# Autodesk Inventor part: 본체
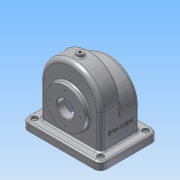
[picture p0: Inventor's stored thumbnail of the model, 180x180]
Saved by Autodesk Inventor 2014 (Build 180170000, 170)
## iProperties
Created: 2017-11
Part Number: 본체
Material: 알루미늄 6061
Document SubType Name: Modeling
Designer: sda
Density: 2.71 g/cm^3
Appearance: 알루미늄 - 평지
Mass: 1079.27 g
Surface Area: 1180.72 cm^2
Volume: 398.255 cm^3
Author: sda
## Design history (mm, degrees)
sketch "스케치1"
  geometry: L1 (-58, 0)-(58, 0); L2 (58, 0)-(58, -80); L3 (58, -80)-(-58, -80); L4 (-58, -80)-(-58, 0); C1 r 58 at (0, 0); 2 further points
  constraints: 8 end point, 2 coincident, 2 parallel, 1 centre point, 1 horizontal, 1 midpoint, 1 perpendicular
  dimensions: "d0" = 80 distance of L1.end L2.end; "d1" = 116 distance of L2.end L3.end; "d2" = 116 diameter of C1
extrude "돌출1" new body sketch "스케치1" distance "d3" = 38; taper "d4" = 0 deg
sketch "스케치2"
  geometry: L1 (-58, -80)-(58, -80) reference; L2 (58, -80)-(58, 0) reference; L3 (-58, -23)-(58, -23); L4 (58, -23)-(58, -80); L5 (58, -80)-(-58, -80); L6 (-58, -80)-(-58, -23); A1 r 58 centre (0, -23) between (58, -23) and (-10.724, -80); A2 r 58 centre (0, -23) between (10.724, -80) and (58, -23); A3 r 58 centre (0, -23) between (-10.724, -80) and (10.724, -80); 1 further point
  constraints: 8 end point, 6 point on circle, 3 centre point, 3 midpoint, 3 point on line, 2 parallel, 1 horizontal, 1 perpendicular
  dimensions: "d5" = 116 distance of L3.start L3.end; "d6" = 57 distance between parallel lines of L1 L3; "d8" = 58 radius of A2
extrude "돌출2" join sketch "스케치2" distance "d9" = 38; taper "d10" = 0 deg
sketch "스케치3"
  geometry: L1 (-58, -80)-(58, -80) reference; C1 r 37.5 at (0, -15); A1 r 58 centre (0, 0) between (58, 0) and (-58, 0) reference
  constraints: 1 centre point, 1 vertical alignment
  dimensions: "d11" = 75 diameter of C1; "d12" = 65 distance from line of C1.centre L1
extrude "돌출3" join sketch "스케치3" distance "d13" = 9; taper "d14" = 0 deg
sketch "스케치4"
  geometry: L1 (-58, -80)-(58, -80) reference; C1 r 31 at (0, -15); 1 further point
  constraints: 1 centre point, 1 vertical alignment
  dimensions: "d15" = 62 diameter of C1; "d16" = 65 distance from line of L1 C1.centre
extrude "돌출4" join sketch "스케치4" distance "d17" = 10; taper "d18" = 0 deg
node "작업 평면1"
node "작업 평면2"
sketch "스케치10"
  geometry: L1 (116, 0)-(116, -76) reference; L2 (0, 0)-(116, 0) reference; L3 (0, 0)-(0, -76) reference; L4 (116, -76)-(0, -76) reference; L5 (-17, 17)-(133, 17); L6 (133, 17)-(133, -93); L7 (133, -93)-(-17, -93); L8 (-17, -93)-(-17, 17); 3 further points
  constraints: 8 end point, 2 midpoint, 2 parallel, 1 horizontal, 1 horizontal alignment, 1 perpendicular, 1 vertical alignment
  dimensions: "d57" = 110 distance of L7.end L5.start; "d58" = 150 distance of L5.start L5.end
extrude "돌출8" join sketch "스케치10" distance "d59" = 15; taper "d60" = 0 deg
sketch "스케치14"
  geometry: L1 (58, 38)-(-58, 38) reference; L2 (75, -55)-(75, 55) reference; C1 r 6 at (0, 19); 1 further point
  constraints: 1 centre point
  dimensions: "d72" = 12 diameter of C1; "d73" = 19 distance from line of L1 C1.centre; "d74" = 75 distance from line of C1.centre L2
extrude "돌출11" join sketch "스케치14" distance "d75" = 64; taper "d76" = 0 deg
sketch "스케치15"
  geometry: L1 (75, -65)-(75, -80) reference; L2 (75, -80)-(-75, -80) reference; L3 (-75, -80)-(-75, -65) reference; L4 (-75, -65)-(-58, -65) reference; L5 (-58, -65)-(-58, 0) reference; L6 (-6, 57.689)-(-6, 64) reference; L7 (-6, 64)-(6, 64) reference; L8 (6, 64)-(6, 57.689) reference; L9 (58, 0)-(58, -65) reference; L10 (58, -65)-(75, -65) reference; L11 (53, 0)-(53, -80); L12 (-53, -80)-(-53, 0); A1 r 58 centre (0, 0) between (-6, 57.689) and (-58, 0) reference; A2 r 58 centre (0, 0) between (58, 0) and (6, 57.689) reference; A3 r 58 centre (0, 0) between (58, 0) and (-58, 0) reference; A4 r 53 centre (0, 0) between (53, 0) and (-53, 0); 1 further point
  constraints: 4 end point, 2 point on circle, 2 point on line, 1 centre point
  dimensions: "d77" = 5 radial gap between concentric circles of A2 A4; "d78" = 5 distance between parallel lines of L9 L11; "d79" = 5 distance between parallel lines of L5 L12
extrude "돌출12" cut sketch "스케치15" stored distance "d80" = 28; taper "d81" = 0 deg
sketch "스케치16"
  geometry: L1 (75, -65)-(75, -80) reference; L2 (75, -80)-(-75, -80) reference; L3 (-75, -80)-(-75, -65) reference; L4 (-75, -65)-(-58, -65) reference; L5 (-58, -65)-(-58, -23) reference; L6 (58, -23)-(58, -65) reference; L7 (58, -65)-(75, -65) reference; L8 (-53, -23)-(-53, -80); L9 (53, -80)-(53, -23); A1 r 58 centre (0, -23) between (58, -23) and (-58, -23) reference; A2 r 53 centre (0, -23) between (53, -23) and (-53, -23); 1 further point
  constraints: 4 end point, 2 point on circle, 2 point on line, 1 centre point, 1 other
  dimensions: "d82" = 5 radial gap between concentric circles of A1 A2; "d83" = 5 distance between parallel lines of L5 L8
extrude "돌출13" cut sketch "스케치16" distance "d84" = 28; taper "d86" = 0 deg; dims "d85" = 14, "d87" = 0
fillet "모깎기3" dims "d88" = 3
sketch "스케치17"
  geometry: C1 r 37.5 at (0, 0) reference; C2 r 16 at (0, 0); 1 further point
  constraints: 1 centre point, 1 coincident
  dimensions: "d89" = 32 diameter of C2
extrude "돌출14" cut sketch "스케치17" stored distance "d90" = 28; taper "d91" = 0 deg
sketch "스케치18" dims "d92" = 58
  geometry: C1 r 16 at (0, 0) reference; C2 r 37.5 at (0, 0) reference; 3 further points
  constraints: 2 vertical alignment, 1 coincident, 2 other
hole "구멍3" sketch "스케치18" at (0, 29) diameter "d93" = 2.459; stored, may be unused: countersink angle "d97" = 90 deg, drill point angle "d99" = 118 deg; dims "d94" = 6, "d95" = 4, "d96" = 2, "d98" = 8
sketch "스케치19" dims "d103" = 52
  geometry: C1 r 16 at (0, 0) reference; C2 r 31 at (0, 0) reference; 3 further points
  constraints: 2 vertical alignment, 1 coincident, 2 other
hole "구멍4" sketch "스케치19" at (0, 26) diameter "d104" = 2.459; stored, may be unused: countersink angle "d108" = 90 deg, drill point angle "d110" = 118 deg; dims "d105" = 6, "d106" = 4, "d107" = 2, "d109" = 8
sketch "스케치20"
  geometry: L1 (-17, -17)-(133, -17) reference; L2 (133, -17)-(133, 93) reference; C1 r 6 at (121, -5); 1 further point
  constraints: 1 centre point
  dimensions: "d114" = 12 diameter of C1; "d115" = 12 distance from line of L1 C1.centre; "d116" = 12 distance from line of L2 C1.centre
extrude "돌출15" cut sketch "스케치20" distance "d117" = 5; taper "d118" = 0 deg
sketch "스케치21"
  geometry: C1 r 6 at (0, 0) reference; C2 r 2.5 at (0, 0); 1 further point
  constraints: 1 centre point, 1 coincident
  dimensions: "d119" = 5 diameter of C2
extrude "돌출16" cut sketch "스케치21" stored distance "d120" = 5; taper "d121" = 0 deg
sketch "스케치22"
  geometry: C1 r 6 at (0, 0) reference; C2 r 2.5 at (0, 0); 1 further point
  constraints: 1 centre point, 1 coincident
  dimensions: "d128" = 5 diameter of C2
extrude "돌출17" cut sketch "스케치22" distance "d129" = 118.75; taper "d130" = 0 deg
feature "스레드1" dims "d131" = 10, "d132" = 0
chamfer "모따기1" distance "d133" = 1; stored, may be unused: second distance "d134" = 2, angle "d135" = 45 deg
fillet "모깎기4" dims "d136" = 12
fillet "모깎기5" dims "d137" = 8
fillet "모깎기6" dims "d138" = 3
node "작업 평면3"
sketch "스케치23"
  geometry: L1 (-13, -18)-(73, -18) reference; L2 (-8, 62)-(-8, 0) reference; 2 further points
  constraints: 1 other
  dimensions: "d140" = 40 distance from line of L1 point (30, 22); "d141" = 38 distance from line of point (30, 22) L2
feature "엠보싱1" sketch "스케치23" dims "d0" = 80, "d1" = 116, "d2" = 116, "d142" = 0.5, "d143" = 0
node "솔리드1"
pattern_circular "원형 패턴3" dims angle "d101" = 360 deg
pattern_circular "원형 패턴4" dims angle "d112" = 360 deg
pattern_linear "직사각형 패턴1" dims "d124" = 86, "d127" = 126
node "절단 모서리 투영5"
node "절단 모서리 투영6"
other parameters: "d19" = 19, "d24" = -19, "d139" = 62.5
